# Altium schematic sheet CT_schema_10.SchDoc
size 274 x 160 mm
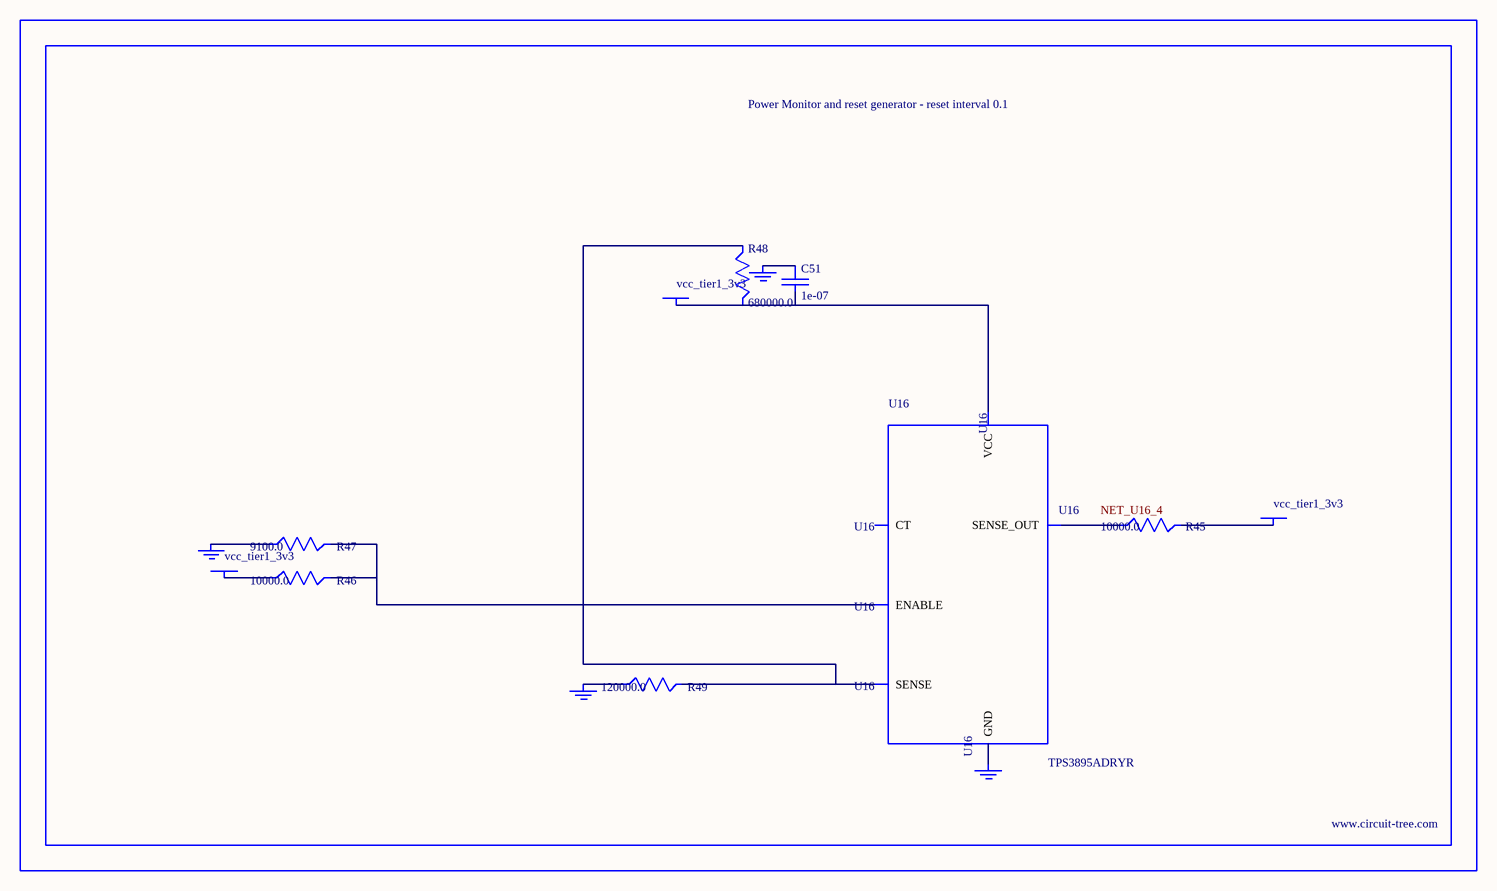
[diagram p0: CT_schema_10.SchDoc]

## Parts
BORDER9  (no value)
C51  1e-07  [C0402]
GND_INSTANCE_9_0  (no value)
GND_INSTANCE_9_1  (no value)
GND_INSTANCE_9_2  (no value)
GND_INSTANCE_9_3  (no value)
POWER_INSTANCE_9_0  vcc_tier1_3v3
POWER_INSTANCE_9_1  vcc_tier1_3v3
POWER_INSTANCE_9_2  vcc_tier1_3v3
R45  10000.0  [R0603]
R46  10000.0  [R0603]
R47  9100.0  [R0603]
R48  680000.0  [R0603]
R49  120000.0  [R0603]
U16  TPS3895ADRYR  [SON-6]

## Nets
NetC51_1: C51.1 GND_INSTANCE_9_2.0(GND)
NetC51_2: C51.2 POWER_INSTANCE_9_2.0(PWR) R48.2 U16.6(VCC)
NetGND_INSTANCE_9_0_0: GND_INSTANCE_9_0.0(GND) R47.1
NetGND_INSTANCE_9_1_0: GND_INSTANCE_9_1.0(GND) R49.1
NetGND_INSTANCE_9_3_0: GND_INSTANCE_9_3.0(GND) U16.2(GND)
NetPOWER_INSTANCE_9_0_0: POWER_INSTANCE_9_0.0(PWR) R46.1
NetPOWER_INSTANCE_9_1_0: POWER_INSTANCE_9_1.0(PWR) R45.2
NetR45_1: R45.1 U16.4(SENSE_OUT)
NetR46_2: R46.2 R47.2 U16.1(ENABLE)
NetR48_1: R48.1 R49.2 U16.3(SENSE)

Not connected (* = marked no-connect by the designer): U16 5(CT)

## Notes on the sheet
- Labels drawn without touching a wire or pin: NET_U16_4

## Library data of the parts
BORDER9 = BORDER_PAGE9
C51 = C0402C104K3RACTU
GND_INSTANCE_9_0-GND_INSTANCE_9_3 = GND
POWER_INSTANCE_9_0-POWER_INSTANCE_9_2 = PWR
R45 R46 = RC0603JR-0710KL
R47 = RC0603JR-079K1L
R48 = RC0603JR-07680KL
R49 = RC0603JR-07120KL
